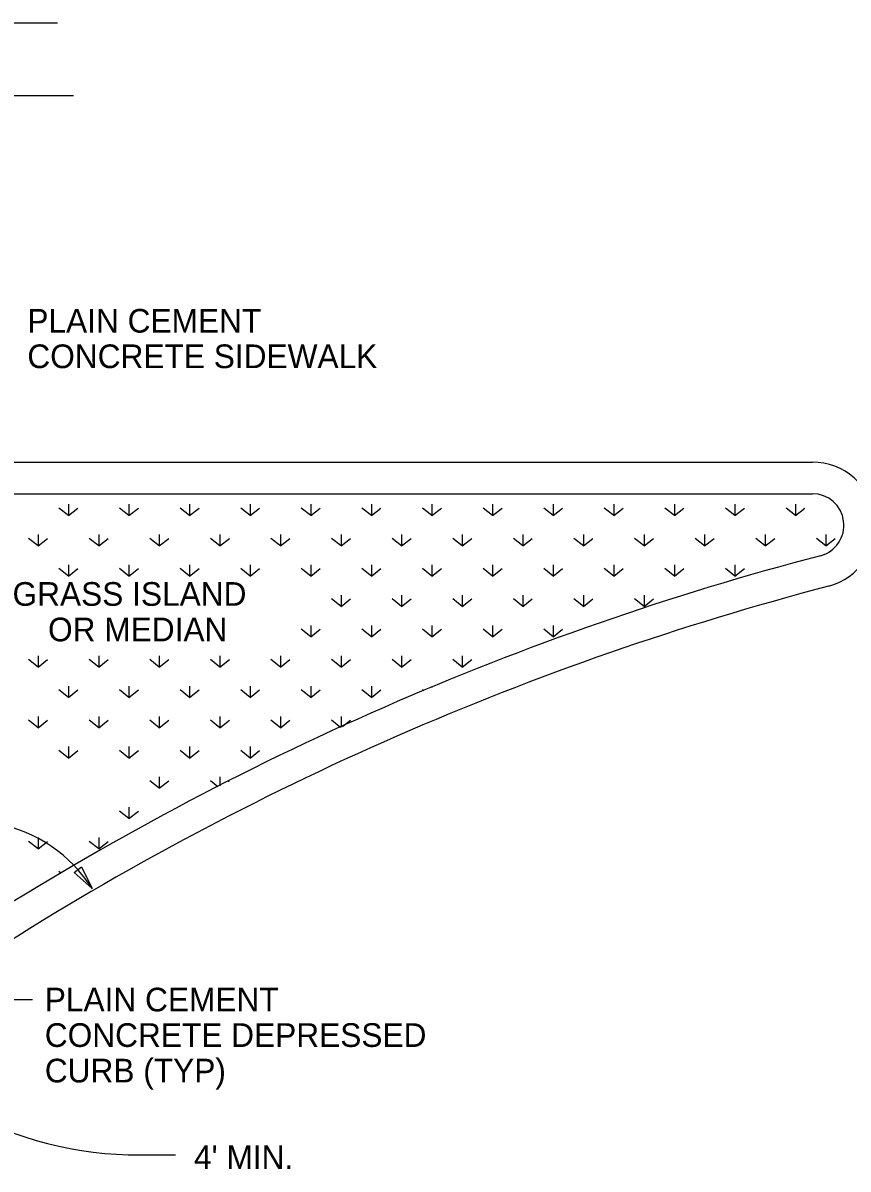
# Model space of a CAD drawing. Extents: x 36 to 940, y -1166 to 1210.
# Drawn here: x 556.7 to 661.3, y -1052.9 to -907.7 of the extents above; entities that cross this region are included whole.
import ezdxf

# ---------------------------------------------------------------- set-up
doc = ezdxf.new("R2010")
doc.units = 0
doc.layers.add('2', color=7, linetype='Continuous')
doc.layers.add('Default', color=7, linetype='Continuous')

msp = doc.modelspace()

# ---------------------------------------------------------------- linework, layer by layer
at = {"layer": '2'}
for p, q in [((416.96, -907.66), (561.11, -907.66)), ((414.51, -916.87), (563.16, -916.87))]:
    msp.add_line(p, q, dxfattribs=at)
at = {"layer": 'Default'}
for p, q in [((452.2, -963.32), (656.79, -963.32)), ((452.2, -967.32), (656.79, -967.32)), ((562.5, -968.66), (562.5, -970.1)), ((570.18, -968.66), (570.18, -970.1)), ((577.86, -968.66), (577.86, -970.1)), ((585.54, -968.66), (585.54, -970.1)), ((593.22, -968.66), (593.22, -970.1)), ((600.9, -968.66), (600.9, -970.1)), ((608.58, -968.66), (608.58, -970.1)), ((616.26, -968.66), (616.26, -970.1)), ((623.94, -968.66), (623.94, -970.1)), ((631.62, -968.66), (631.62, -970.1)), ((639.3, -968.66), (639.3, -970.1)), ((646.98, -968.66), (646.98, -970.1)), ((654.66, -968.66), (654.66, -970.1)), ((562.5, -970.1), (561.3, -969.14)), ((562.5, -970.1), (563.7, -969.14)), ((570.18, -970.1), (568.98, -969.14)), ((570.18, -970.1), (571.38, -969.14)), ((577.86, -970.1), (576.66, -969.14)), ((577.86, -970.1), (579.06, -969.14)), ((585.54, -970.1), (584.34, -969.14)), ((585.54, -970.1), (586.74, -969.14)), ((593.22, -970.1), (592.02, -969.14)), ((593.22, -970.1), (594.42, -969.14)), ((600.9, -970.1), (599.7, -969.14)), ((600.9, -970.1), (602.1, -969.14)), ((608.58, -970.1), (607.38, -969.14)), ((608.58, -970.1), (609.78, -969.14)), ((616.26, -970.1), (615.06, -969.14)), ((616.26, -970.1), (617.46, -969.14)), ((623.94, -970.1), (622.74, -969.14)), ((623.94, -970.1), (625.14, -969.14)), ((631.62, -970.1), (630.42, -969.14)), ((631.62, -970.1), (632.82, -969.14)), ((639.3, -970.1), (638.1, -969.14)), ((639.3, -970.1), (640.5, -969.14)), ((646.98, -970.1), (645.78, -969.14)), ((646.98, -970.1), (648.18, -969.14)), ((654.66, -970.1), (653.46, -969.14)), ((654.66, -970.1), (655.86, -969.14)), ((558.66, -973.94), (557.46, -972.98)), ((558.66, -972.5), (558.66, -973.94)), ((558.66, -973.94), (559.86, -972.98)), ((566.34, -973.94), (565.14, -972.98)), ((566.34, -972.5), (566.34, -973.94)), ((566.34, -973.94), (567.54, -972.98)), ((574.02, -973.94), (572.82, -972.98)), ((574.02, -972.5), (574.02, -973.94)), ((574.02, -973.94), (575.22, -972.98)), ((581.7, -973.94), (580.5, -972.98)), ((581.7, -972.5), (581.7, -973.94)), ((581.7, -973.94), (582.9, -972.98)), ((589.38, -973.94), (588.18, -972.98)), ((589.38, -972.5), (589.38, -973.94)), ((589.38, -973.94), (590.58, -972.98)), ((597.06, -973.94), (595.86, -972.98)), ((597.06, -972.5), (597.06, -973.94)), ((597.06, -973.94), (598.26, -972.98)), ((604.74, -973.94), (603.54, -972.98)), ((604.74, -972.5), (604.74, -973.94)), ((604.74, -973.94), (605.94, -972.98)), ((612.42, -973.94), (611.22, -972.98)), ((612.42, -972.5), (612.42, -973.94)), ((612.42, -973.94), (613.62, -972.98)), ((620.1, -973.94), (618.9, -972.98)), ((620.1, -972.5), (620.1, -973.94)), ((620.1, -973.94), (621.3, -972.98)), ((627.78, -973.94), (626.58, -972.98)), ((627.78, -972.5), (627.78, -973.94)), ((627.78, -973.94), (628.98, -972.98)), ((635.46, -973.94), (634.26, -972.98)), ((635.46, -972.5), (635.46, -973.94)), ((635.46, -973.94), (636.66, -972.98)), ((643.14, -973.94), (641.94, -972.98)), ((643.14, -972.5), (643.14, -973.94)), ((643.14, -973.94), (644.34, -972.98)), ((650.82, -973.94), (649.62, -972.98)), ((650.82, -972.5), (650.82, -973.94)), ((650.82, -973.94), (652.02, -972.98)), ((658.5, -973.94), (657.3, -972.98)), ((658.5, -972.5), (658.5, -973.94)), ((658.5, -973.94), (659.7, -972.98)), ((562.5, -977.78), (561.3, -976.82)), ((562.5, -976.34), (562.5, -977.78)), ((562.5, -977.78), (563.7, -976.82)), ((570.18, -977.78), (568.98, -976.82)), ((570.18, -976.34), (570.18, -977.78)), ((570.18, -977.78), (571.38, -976.82)), ((577.86, -977.78), (576.66, -976.82)), ((577.86, -976.34), (577.86, -977.78)), ((577.86, -977.78), (579.06, -976.82)), ((585.54, -977.78), (584.34, -976.82)), ((585.54, -976.34), (585.54, -977.78)), ((585.54, -977.78), (586.74, -976.82)), ((593.22, -977.78), (592.02, -976.82)), ((593.22, -976.34), (593.22, -977.78)), ((593.22, -977.78), (594.42, -976.82)), ((600.9, -977.78), (599.7, -976.82)), ((600.9, -976.34), (600.9, -977.78)), ((600.9, -977.78), (602.1, -976.82)), ((608.58, -977.78), (607.38, -976.82)), ((608.58, -976.34), (608.58, -977.78)), ((608.58, -977.78), (609.78, -976.82)), ((616.26, -977.78), (615.06, -976.82)), ((616.26, -976.34), (616.26, -977.78)), ((616.26, -977.78), (617.46, -976.82)), ((623.94, -977.78), (622.74, -976.82)), ((623.94, -976.34), (623.94, -977.78)), ((623.94, -977.78), (625.14, -976.82)), ((631.62, -977.78), (630.42, -976.82)), ((631.62, -976.34), (631.62, -977.78)), ((631.62, -977.78), (632.82, -976.82)), ((639.3, -977.78), (638.1, -976.82)), ((639.3, -976.34), (639.3, -977.78)), ((639.3, -977.78), (640.5, -976.82)), ((646.98, -977.78), (645.78, -976.82)), ((646.98, -976.34), (646.98, -977.78)), ((646.98, -977.78), (648.18, -976.82)), ((597.06, -980.18), (597.06, -981.62)), ((604.74, -980.18), (604.74, -981.62)), ((612.42, -980.18), (612.42, -981.62)), ((620.1, -980.18), (620.1, -981.62)), ((627.78, -980.18), (627.78, -981.62)), ((635.46, -980.18), (635.46, -981.62)), ((597.06, -981.62), (595.86, -980.66)), ((597.06, -981.62), (598.26, -980.66)), ((604.74, -981.62), (603.54, -980.66)), ((604.74, -981.62), (605.94, -980.66)), ((612.42, -981.62), (611.22, -980.66)), ((612.42, -981.62), (613.62, -980.66)), ((620.1, -981.62), (618.9, -980.66)), ((620.1, -981.62), (621.3, -980.66)), ((627.78, -981.62), (626.58, -980.66)), ((627.78, -981.62), (628.98, -980.66)), ((635.46, -981.62), (634.26, -980.66)), ((635.46, -981.62), (636.66, -980.66)), ((593.22, -985.46), (592.02, -984.5)), ((593.22, -984.02), (593.22, -985.46)), ((593.22, -985.46), (594.42, -984.5)), ((600.9, -985.46), (599.7, -984.5)), ((600.9, -984.02), (600.9, -985.46)), ((600.9, -985.46), (602.1, -984.5)), ((608.58, -985.46), (607.38, -984.5)), ((608.58, -984.02), (608.58, -985.46)), ((608.58, -985.46), (609.78, -984.5)), ((616.26, -985.46), (615.06, -984.5)), ((616.26, -984.02), (616.26, -985.46)), ((616.26, -985.46), (617.46, -984.5)), ((623.94, -985.46), (622.74, -984.5)), ((623.94, -984.02), (623.94, -985.46)), ((623.94, -985.46), (625.14, -984.5)), ((558.66, -989.3), (557.46, -988.34)), ((558.66, -987.86), (558.66, -989.3)), ((558.66, -989.3), (559.86, -988.34)), ((566.34, -989.3), (565.14, -988.34)), ((566.34, -987.86), (566.34, -989.3)), ((566.34, -989.3), (567.54, -988.34)), ((574.02, -989.3), (572.82, -988.34)), ((574.02, -987.86), (574.02, -989.3)), ((574.02, -989.3), (575.22, -988.34)), ((581.7, -989.3), (580.5, -988.34)), ((581.7, -987.86), (581.7, -989.3)), ((581.7, -989.3), (582.9, -988.34)), ((589.38, -989.3), (588.18, -988.34)), ((589.38, -987.86), (589.38, -989.3)), ((589.38, -989.3), (590.58, -988.34)), ((597.06, -989.3), (595.86, -988.34)), ((597.06, -987.86), (597.06, -989.3)), ((597.06, -989.3), (598.26, -988.34)), ((604.74, -989.3), (603.54, -988.34)), ((604.74, -987.86), (604.74, -989.3)), ((604.74, -989.3), (605.94, -988.34)), ((612.42, -989.3), (611.22, -988.34)), ((612.42, -987.86), (612.42, -989.3)), ((612.42, -989.3), (613.62, -988.34)), ((562.5, -991.7), (562.5, -993.14)), ((570.18, -991.7), (570.18, -993.14)), ((577.86, -991.7), (577.86, -993.14)), ((585.54, -991.7), (585.54, -993.14)), ((593.22, -991.7), (593.22, -993.14)), ((600.9, -991.7), (600.9, -993.14)), ((608.58, -991.7), (608.58, -991.88)), ((562.5, -993.14), (561.3, -992.18)), ((562.5, -993.14), (563.7, -992.18)), ((570.18, -993.14), (568.98, -992.18)), ((570.18, -993.14), (571.38, -992.18)), ((577.86, -993.14), (576.66, -992.18)), ((577.86, -993.14), (579.06, -992.18)), ((585.54, -993.14), (584.34, -992.18)), ((585.54, -993.14), (586.74, -992.18)), ((593.22, -993.14), (592.02, -992.18)), ((593.22, -993.14), (594.42, -992.18)), ((600.9, -993.14), (599.7, -992.18)), ((600.9, -993.14), (602.1, -992.18)), ((607.53, -992.3), (607.38, -992.18)), ((558.66, -996.98), (557.46, -996.02)), ((558.66, -995.54), (558.66, -996.98)), ((558.66, -996.98), (559.86, -996.02)), ((566.34, -996.98), (565.14, -996.02)), ((566.34, -995.54), (566.34, -996.98)), ((566.34, -996.98), (567.54, -996.02)), ((574.02, -996.98), (572.82, -996.02)), ((574.02, -995.54), (574.02, -996.98)), ((574.02, -996.98), (575.22, -996.02)), ((581.7, -996.98), (580.5, -996.02)), ((581.7, -995.54), (581.7, -996.98)), ((581.7, -996.98), (582.9, -996.02)), ((589.38, -996.98), (588.18, -996.02)), ((589.38, -995.54), (589.38, -996.98)), ((589.38, -996.98), (590.58, -996.02)), ((597.01, -996.94), (595.86, -996.02)), ((597.06, -995.54), (597.06, -996.92)), ((597.24, -996.83), (598.26, -996.02)), ((562.5, -1000.82), (561.3, -999.86)), ((562.5, -999.38), (562.5, -1000.82)), ((562.5, -1000.82), (563.7, -999.86)), ((570.18, -1000.82), (568.98, -999.86)), ((570.18, -999.38), (570.18, -1000.82)), ((570.18, -1000.82), (571.38, -999.86)), ((577.86, -1000.82), (576.66, -999.86)), ((577.86, -999.38), (577.86, -1000.82)), ((577.86, -1000.82), (579.06, -999.86)), ((585.54, -1000.82), (584.34, -999.86)), ((585.54, -999.38), (585.54, -1000.82)), ((585.54, -1000.82), (586.74, -999.86)), ((574.02, -1003.22), (574.02, -1004.66)), ((581.7, -1003.22), (581.7, -1004.34)), ((574.02, -1004.66), (572.82, -1003.7)), ((574.02, -1004.66), (575.22, -1003.7)), ((581.45, -1004.47), (580.5, -1003.7)), ((582.77, -1003.8), (582.9, -1003.7)), ((570.18, -1008.5), (568.98, -1007.54)), ((570.18, -1007.06), (570.18, -1008.5)), ((570.18, -1008.5), (571.38, -1007.54)), ((558.66, -1010.9), (558.66, -1012.34)), ((566.34, -1010.9), (566.34, -1012.34)), ((558.66, -1012.34), (557.46, -1011.38)), ((558.66, -1012.34), (559.86, -1011.38)), ((566.34, -1012.34), (565.14, -1011.38)), ((566.34, -1012.34), (567.54, -1011.38)), ((561.55, -1015.42), (561.3, -1015.22)), ((562.5, -1014.74), (562.5, -1014.85)), ((557.97, -1031.45), (540.45, -1031.45)), ((570.09, -1051.09), (576.06, -1051.09))]:
    msp.add_line(p, q, dxfattribs=at)
msp.add_lwpolyline([(564.17, -1014.59), (565.51, -1017.34), (563.22, -1015.32)], close=True, dxfattribs=at)
for centre, radius, start, end in [((656.79, -971.32), 8, 284.7063, 90), ((656.79, -971.32), 4, 284.7063, 90), ((753.46, -1339.64), 376.8, 104.7063, 122.5261), ((753.46, -1339.64), 372.8, 104.7063, 122.5261), ((549.92, -1027.29), 18.49, 32.5261, 124.9342), ((571.07, -1006.38), 44.72, 238.3693, 268.7424)]:
    msp.add_arc(centre, radius, start, end, dxfattribs=at)

# ---------------------------------------------------------------- texts
for s, p in [('PLAIN CEMENT', (557.3, -946.91)), ('CONCRETE SIDEWALK', (557.3, -951.41)), ('GRASS ISLAND', (555.42, -981.53)), ('OR MEDIAN', (559.92, -986.03)), ('PLAIN CEMENT', (559.51, -1032.93)), ('CONCRETE DEPRESSED', (559.51, -1037.43)), ('CURB (TYP)', (559.51, -1041.93)), ("4' MIN.", (578.42, -1052.91))]:
    msp.add_text(s, height=3, dxfattribs=at).set_placement(p)

doc.saveas('drawing.dxf')
